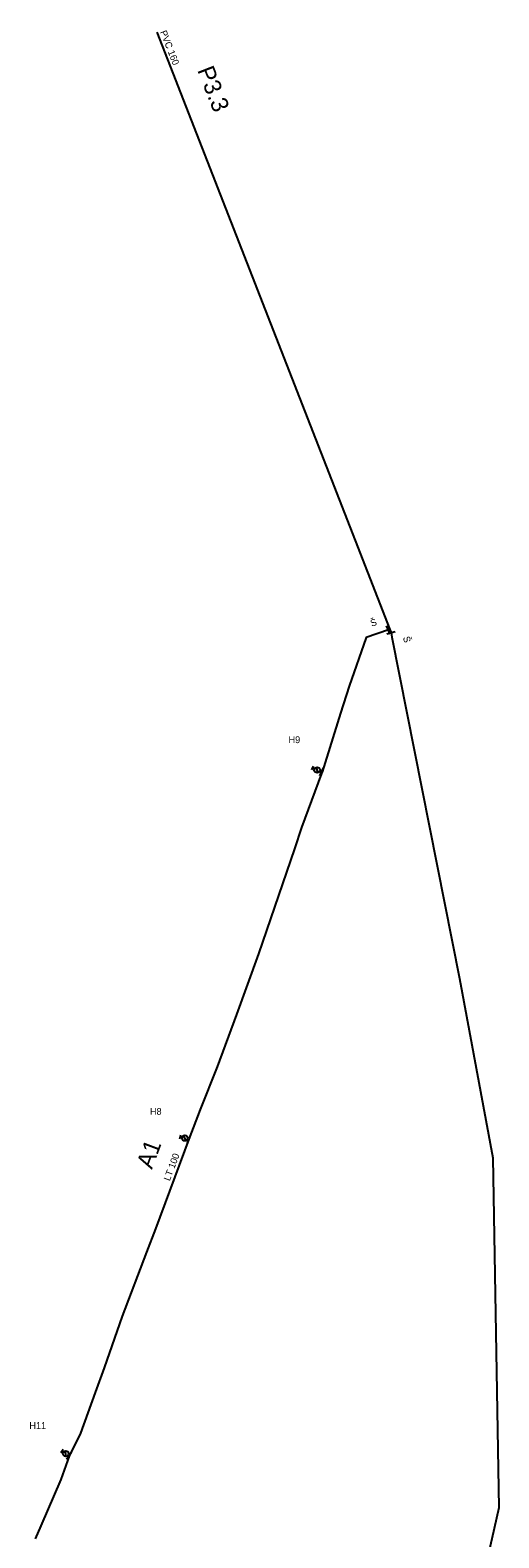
# Model space of a CAD drawing. Extents: x -574447 to -573745, y -1188179 to -1187219.
# Drawn here: x -573882.8 to -573745, y -1187661.9 to -1187218.6 of the extents above; entities that cross this region are included whole.
import ezdxf

# ---------------------------------------------------------------- set-up
doc = ezdxf.new("R2010")
doc.units = 0
for name, color, linetype in [('Vrstva 1', 7, 'Continuous'), ('Vrstva 15', 7, 'Continuous'), ('Vrstva 19', 7, 'Continuous'), ('Vrstva 25', 7, 'Continuous'), ('Vrstva 28', 7, 'Continuous'), ('Vrstva 29', 7, 'Continuous'), ('Vrstva 35', 7, 'Continuous')]:
    doc.layers.add(name, color=color, linetype=linetype)

# ---------------------------------------------------------------- blocks, each defined once
blk = doc.blocks.new('160')
at = {"layer": 'Vrstva 1'}
blk.add_circle((0, 0), 0.0458, dxfattribs=at)
blk = doc.blocks.new('147')
at = {"layer": 'Vrstva 1'}
blk.add_line((0, 1.27), (0, -1.27), dxfattribs=at)
blk = doc.blocks.new('133')
at = {"layer": 'Vrstva 1'}
for p, q in [((0.28, 0), (0, 0)), ((0.54, 0.58), (1.7, -0.58)), ((1.94, 0), (2.52, 0)), ((2.52, 0.58), (2.52, -0.58))]:
    blk.add_line(p, q, dxfattribs=at)
blk.add_circle((1.105, 0.003), 0.825, dxfattribs=at)
blk = doc.blocks.new('150')
at = {"layer": 'Vrstva 1'}
blk.add_line((0, 1.27), (0, -1.27), dxfattribs=at)

msp = doc.modelspace()

# ---------------------------------------------------------------- linework, layer by layer
at = {"layer": 'Vrstva 15'}
msp.add_line((-573777.065, -1187394.805), (-573777.49, -1187394.97), dxfattribs=at)
msp.add_lwpolyline([(-573777.49, -1187394.97), (-573784.04, -1187397.15), (-573789.05, -1187411.46), (-573791.554, -1187419.444), (-573796.978, -1187436.742), (-573797.135, -1187437.175), (-573803.015, -1187453.091), (-573805.125, -1187459.292), (-573815.632, -1187490.17), (-573822.171, -1187508.049), (-573827.853, -1187523.449), (-573832.844, -1187535.946), (-573836.15, -1187544.67), (-573845.987, -1187571.002), (-573848.567, -1187577.909), (-573855.723, -1187596.717), (-573861.08, -1187611.862), (-573863.671, -1187619.15), (-573868.005, -1187631.109), (-573871.361, -1187637.838), (-573873.805, -1187644.782), (-573879.671, -1187658.332), (-573881.35, -1187662.21)], dxfattribs=at)
at = {"layer": 'Vrstva 19'}
msp.add_line((-573777.065, -1187394.805), (-573776.7, -1187395.74), dxfattribs=at)
for points in [[(-573845.598, -1187219.219), (-573787.267, -1187368.668), (-573777.065, -1187394.805)], [(-573776.7, -1187395.74), (-573776.433, -1187397.089), (-573756.58, -1187497.42), (-573746.79, -1187550.13), (-573745, -1187653.04), (-573765.99, -1187745.82), (-573827.995, -1187937.981), (-573851.222, -1188009.966), (-573853.24, -1188016.22), (-573855.495, -1188023.056)]]:
    msp.add_lwpolyline(points, dxfattribs=at)
at = {"layer": 'Vrstva 25'}
for p, q in [((-573796.993, -1187436.79), (-573797.403, -1187436.627)), ((-573836.15, -1187544.67), (-573836.241, -1187544.646)), ((-573871.361, -1187637.838), (-573871.452, -1187637.772))]:
    msp.add_line(p, q, dxfattribs=at)

# ---------------------------------------------------------------- block references
for name, p, xscale, yscale, rotation in [('133', (-573797.403, -1187436.627), 1.025136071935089, 1.0251360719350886, 154.74924162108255), ('150', (-573797.198, -1187436.708), 1.022584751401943, 1.022584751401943, -25.818974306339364), ('133', (-573836.241, -1187544.646), 0.999999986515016, 0.9999999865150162, 164.99999987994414), ('150', (-573836.195, -1187544.658), 1.0365458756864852, 1.0365458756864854, -21.97149085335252), ('133', (-573871.452, -1187637.772), 0.9999999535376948, 0.9999999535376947, 143.99999865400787), ('150', (-573871.406, -1187637.805), 0.9999999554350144, 0.9999999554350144, -36.99999920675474)]:
    msp.add_blockref(name, p, dxfattribs=dict(at, xscale=xscale, yscale=yscale, rotation=rotation))
at = {"layer": 'Vrstva 29'}
for name, p, xscale, yscale, rotation in [('147', (-573777.49, -1187394.97), 1.0316957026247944, 1.0316957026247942, -156.4154111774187), ('147', (-573776.7, -1187395.74), 0.9999999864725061, 0.9999999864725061, 105.99999860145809), ('160', (-573777.065, -1187394.805), 0.999999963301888, 0.9999999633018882, 110.99999898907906)]:
    msp.add_blockref(name, p, dxfattribs=dict(at, xscale=xscale, yscale=yscale, rotation=rotation))

# ---------------------------------------------------------------- texts
at = {"layer": 'Vrstva 25'}
for s, p in [('H9', (-573806.833, -1187428.247)), ('H8', (-573847.581, -1187537.516)), ('H11', (-573883.032, -1187629.862))]:
    msp.add_text(s, height=2, dxfattribs=at).set_placement(p)
at = {"layer": 'Vrstva 28'}
for rotation, p in [(19.31, (-573782.372, -1187394.042)), (286.76, (-573773.236, -1187397.184))]:
    msp.add_text('Š', height=2, rotation=rotation, dxfattribs=at).set_placement(p)
at = {"layer": 'Vrstva 35'}
for s, height, rotation, p in [('PVC 160', 2, 291.32, (-573844.651, -1187219.158)), ('P3.3', 5, 291.32, (-573833.729, -1187230.372)), ('A1', 5, 69.52, (-573847.006, -1187553.728)), ('LT 100', 2, 69.52, (-573841.761, -1187557.107))]:
    msp.add_text(s, height=height, rotation=rotation, dxfattribs=at).set_placement(p)

doc.saveas('drawing.dxf')
